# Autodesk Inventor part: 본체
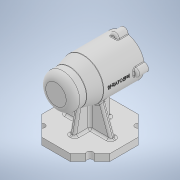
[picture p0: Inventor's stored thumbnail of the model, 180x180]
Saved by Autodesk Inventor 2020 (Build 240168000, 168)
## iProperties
Created: 2021-01
Part Number: 본체
Material: 일반
Document SubType Name: Modeling
Designer: USER
Density: 1 g/cm^3
Appearance: 기본값
Author: USER
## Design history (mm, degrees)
sketch "스케치1"
  geometry: L1 (0, 50)-(25, 50); L2 (25, 50)-(25, 30); L3 (25, 30)-(30, 10); L4 (30, 10)-(30, -50); L5 (30, -50)-(21, -50); L6 (21, -50)-(21, -35); L7 (21, -35)-(21, -35); L8 (24, -32)-(24, 4); L9 (21, 7)-(21, 7); L10 (21, 7)-(21, 18.7); L11 (20.7, 19)-(17.5, 19); L12 (17.5, 19)-(17.5, 36.7); L13 (17.2, 37)-(16, 37); L14 (16, 37)-(16, 40.7); L15 (15.7, 41)-(10.5, 41); L16 (10.5, 41)-(10.5, 41); L17 (7.5, 44)-(0, 44); L18 (0, 44)-(0, 50); A1 r 3 centre (21, 4) between (24, 4) and (21, 7); A2 r 3 centre (21, -32) between (21, -35) and (24, -32); A3 r 0.3 centre (15.7, 40.7) between (16, 40.7) and (15.7, 41); A4 r 0.3 centre (17.2, 36.7) between (17.5, 36.7) and (17.2, 37); A5 r 0.3 centre (20.7, 18.7) between (21, 18.7) and (20.7, 19); A6 r 3 centre (7.5, 41) between (10.5, 41) and (7.5, 44); 10 further points
  constraints: 36 end point, 14 perpendicular, 14 point on line, 12 point on circle, 12 tangent, 6 centre point, 3 equal radius, 1 horizontal, 1 parallel
  dimensions: "d0" = 100 distance between parallel lines of L5 L1; "d1" = 25 distance of L1.start L1.end; "d2" = 24 distance from line of point (0, 0) L8; "d3" = 21 distance from line of L6 point (0, 0); "d4" = 17.5 distance from line of point (0, 0) L12; "d5" = 16 distance from line of point (0, 0) L14; "d6" = 10.5 distance from line of point (0, 0) L16; "d7" = 0 distance from line of point (0, 0) L18; "d8" = 15 distance of L5.end L6.end; "d9" = 42 distance of point (24, -35) point (24, 7); "d10" = 12 distance of L9.end point (21, 19); "d11" = 18 distance of L11.end point (17.5, 37); "d12" = 4 distance of L13.end point (16, 41); "d13" = 3 distance of L15.end point (10.5, 44); "d14" = 40 distance from line of L3.end L1; "d15" = 20 distance of L1.end L2.end; "d16" = 30 horizontal distance of point (0, 0) L3.end; "d17" = 50 vertical distance of point (0, 0) L4.end; "d18" = 3 radius of A1; "d19" = 0.3 radius of A3; "d20" = 3 radius of A6
revolve "회전1" sketch "스케치1" stored, may be unused: angle "d21" = 90 deg
sketch "스케치2"
  geometry: C1 r 30 at (0, 0) reference; C2 r 6 at (30, 0); C3 r 6 at (0, 30); C4 r 6 at (-30, 0); C5 r 6 at (0, -30); 2 further points
  constraints: 4 centre point, 1 horizontal alignment, 10 other
  dimensions: "d22" = 12 diameter of C2; "d25" = 360 deg dimension on C1.centre C2.centre (derived); "d27" = 0 vertical distance of point (0, 0) C2.centre
extrude "돌출1" join sketch "스케치2" distance "d28" = 16; taper "d29" = 0 deg
sketch "스케치3"
  geometry: A1 r 30 centre (0, -30) between (29.4, -24.03) and (5.97, -0.6) reference; 5 further points
  constraints: 5 other
  dimensions: "d30" = 0 vertical distance of point (0, -30) point (30, -30); "d31" = 30 distance of point (0, -30) point (30, -30); "d34" = 360 deg dimension on A1.centre point (30, -30) (derived)
hole "구멍1" sketch "스케치3" at (30, -30), (0, 0), (-30, -30), (0, -60) diameter "d36" = 3.242; stored, may be unused: countersink angle "d40" = 90 deg, drill point angle "d42" = 118 deg; dims "d37" = 8, "d38" = 4, "d39" = 2, "d41" = 10
node "작업 평면1"
sketch "스케치4"
  geometry: L1 (20.711, 50)-(50, 20.711); L2 (50, 20.711)-(50, -20.711); L3 (50, -20.711)-(20.711, -50); L4 (20.711, -50)-(-20.711, -50); L5 (-20.711, -50)-(-50, -20.711); L6 (-50, -20.711)-(-50, 20.711); L7 (-50, 20.711)-(-20.711, 50); L8 (-20.711, 50)-(20.711, 50); C1 r 4.5 at (35.355, -35.355); C2 r 4.5 at (-35.355, -35.355); C3 r 4.5 at (-35.355, 35.355); C4 r 4.5 at (35.355, 35.355); 10 further points
  constraints: 16 end point, 4 centre point, 4 midpoint, 1 coincident, 17 other
  dimensions: "d46" = 50 horizontal distance of L5.end point (0, 0); "d47" = 50 horizontal distance of point (0, 0) L2.end; "d48" = 9 diameter of C1; "d49" = 9 diameter of C2; "d50" = 9 diameter of C3; "d51" = 9 diameter of C4
extrude "돌출2" join sketch "스케치4" distance "d52" = 10; taper "d53" = 0 deg
sketch "스케치6"
  geometry: L1 (-50, -75)-(-50, -65) reference; L2 (-38.537, -65)-(-50, -65) reference; L3 (50, -65)-(38.537, -65) reference; L4 (-19.314, -21.904)-(-35, -65); L5 (19.314, -21.904)-(35, -65); L6 (-35, -65)-(35, -65); L7 (50, -75)-(50, -65) reference; A1 r 29.204 centre (0, 0) between (-19.314, -21.904) and (19.314, -21.904); 1 further point
  constraints: 6 end point, 2 point on circle, 2 point on line, 1 centre point, 1 coincident, 1 collinear
  dimensions: "d64" = 110 deg angle of L4 L2; "d65" = 110 deg angle of L3 L5; "d66" = 15 distance from line of L4.end L1; "d67" = 15 distance from line of L7 L5.end; "d68" = 29.20353 radius of A1
extrude "돌출4" join sketch "스케치6" stored distance "d69" = 8; taper "d70" = 0 deg
sketch "스케치7"
  geometry: L1 (-65, -20.711)-(-65, 20.711) reference; L2 (-25.01, 19.227)-(-65, 27); L3 (-65, 27)-(-65, -27); L4 (-25.01, -27)-(-65, -27); L5 (-25.01, -27)-(-25.01, 19.227); L6 (-30, 10)-(-30, -34) reference; L7 (-75, 50)-(-65, 50) reference; L8 (-75, -50)-(-65, -50) reference; L9 (-65, 38.537)-(-65, 50) reference; 3 further points
  constraints: 8 end point, 2 point on line, 1 parallel, 1 perpendicular
  dimensions: "d75" = 23 distance from line of L2.end L7; "d76" = 23 distance from line of L8 L3.end; "d77" = 101 deg angle of L2 L9; "d79" = 46.22669 distance of L4.start L2.start
extrude "돌출5" join sketch "스케치7" stored distance "d80" = 8; taper "d81" = 0 deg
fillet "모깎기1" dims "d82" = 10
fillet "모깎기2" dims "d83" = 3
fillet "모깎기3" dims "d84" = 1
fillet "모깎기4" dims "d85" = 3
fillet "모깎기5" dims "d86" = 3
chamfer "모따기1" distance "d87" = 1; stored, may be unused: second distance "d88" = 2, angle "d89" = 45 deg
node "작업 평면2"
sketch "스케치8"
  geometry: L1 (30.171, -50)-(36, -50) reference; 2 further points
  constraints: 1 other
  dimensions: "d92" = 38 distance from line of L1 point (0, -12); "d93" = 0 horizontal distance of point (0, 0) point (0, -12)
feature "엠보싱1" sketch "스케치8" dims "d0" = 100, "d1" = 25, "d2" = 24, "d3" = 21, "d4" = 17.5, "d5" = 16, "d6" = 10.5, "d7" = 0, "d8" = 15, "d9" = 42, "d10" = 12, "d11" = 18, "d12" = 4, "d13" = 3, "d14" = 40, "d15" = 20, "d16" = 30, "d17" = 50, "d18" = 3, "d19" = 0.3, "d20" = 3, "d94" = 0.5, "d95" = 0
node "솔리드1"
feature "A9D066F2-1C7D-4E18-AEED-F7BC21143FA4" dims "d36" = 3.242, "d37" = 8, "d38" = 4, "d39" = 2, "d40" = 90 deg, "d41" = 10, "d42" = 118 deg
other parameters: "d43" = -75
